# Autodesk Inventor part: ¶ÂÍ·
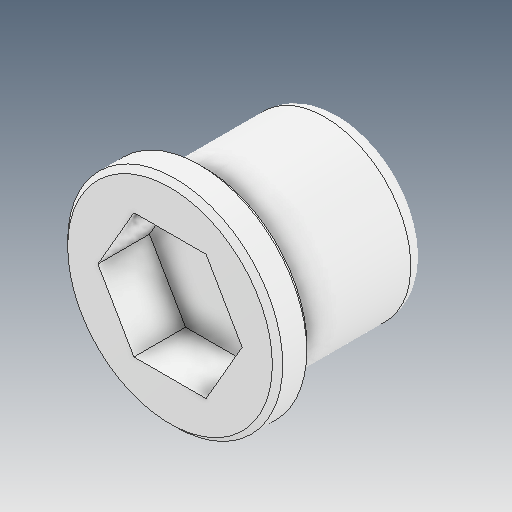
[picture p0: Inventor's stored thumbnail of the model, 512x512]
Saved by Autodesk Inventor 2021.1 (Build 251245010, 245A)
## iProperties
Created: 2021-06
Part Number: ¶ÂÍ·
Material: Ogólny
Document SubType Name: Modeling
Designer: user
Density: 1 g/cm^3
Appearance: Domyślna
Author: user
Revision Number: ÈÎºÎ
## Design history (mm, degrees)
feature "ÊäÈë1"
node "Bryła1"
